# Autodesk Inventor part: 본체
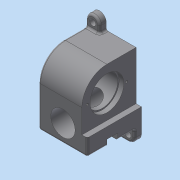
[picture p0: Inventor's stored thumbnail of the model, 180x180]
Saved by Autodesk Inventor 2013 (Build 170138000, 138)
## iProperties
Created: 2019-06
Part Number: 본체
Material: 알루미늄 6061
Document SubType Name: Modeling
Designer: mduedu
Density: 2.71 g/cm^3
Mass: 866.333 g
Surface Area: 555.001 cm^2
Volume: 319.68 cm^3
Author: mduedu
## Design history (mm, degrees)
sketch "스케치1"
  geometry: L1 (37, 0)-(37, -43); L2 (37, -43)-(-60, -43); L3 (-60, -43)-(-60, 37); L4 (-60, 37)-(0, 37); A1 r 37 centre (0, 0) between (37, 0) and (0, 37); 1 further point
  constraints: 8 end point, 2 point on circle, 2 tangent, 1 centre point, 1 coincident, 1 horizontal, 1 parallel, 1 perpendicular, 1 vertical
  dimensions: "d0" = 37 radius of A1; "d2" = 80 distance of L2.end L3.end; "d3" = 97 distance of L1.end L2.end
extrude "돌출1" new body sketch "스케치1" stored distance "d4" = 72; taper "d5" = 0 deg
sketch "스케치2"
  geometry: L1 (72, 25)-(64, 25); L2 (64, 25)-(64, 97); L3 (64, 97)-(72, 97); L4 (72, 97)-(72, 25); L5 (72, 97)-(0, 97) reference; L6 (72, 60)-(72, 0) reference; 1 further point
  constraints: 8 end point, 2 collinear, 2 parallel, 1 horizontal, 1 perpendicular
  dimensions: "d6" = 72 distance between parallel lines of L1 L3; "d8" = 8 distance of L1.start L1.end
extrude "돌출2" cut sketch "스케치2" stored distance "d9" = 72; taper "d10" = 0 deg
sketch "스케치3"
  geometry: L1 (-36, -60)-(-36, 37) reference; L2 (-36, 37)-(28, 37) reference; L3 (28, 37)-(28, -35) reference; L4 (28, -35)-(36, -35) reference; L5 (36, -35)-(36, -60) reference; L6 (36, -60)-(-36, -60) reference; L7 (-36, 0)-(-19, 0); L8 (-19, 0)-(-19, 17.5); L9 (-19, 17.5)-(-36, 17.5); L10 (-36, 17.5)-(-36, 0); L11 (-19, 0)-(21, 0); L12 (21, 0)-(21, 23); L13 (21, 23)-(-19, 23); L14 (-19, 23)-(-19, 0); L15 (21, 0)-(28, 0); L16 (28, 0)-(28, 25); L17 (28, 25)-(21, 25); L18 (21, 25)-(21, 0); 1 further point
  constraints: 24 end point, 6 parallel, 3 horizontal, 3 perpendicular, 2 point on line, 1 horizontal alignment
  dimensions: "d11" = 7 distance of L16.end L17.end; "d13" = 47 distance between parallel lines of L3 L8; "d14" = 50 diameter of L17 L15; "d15" = 46 diameter of L13 L11; "d16" = 35 diameter of L9 L7
revolve "회전1" sketch "스케치3" stored, may be unused: angle "d17" = 90 deg
sketch "스케치4"
  geometry: C1 r 28 at (0, 0); 1 further point
  constraints: 1 centre point, 1 coincident
  dimensions: "d18" = 56 diameter of C1
extrude "돌출3" cut sketch "스케치4" distance "d19" = 2; taper "d20" = 0 deg
fillet "모깎기1" dims "d21" = 3
sketch "스케치5"
  geometry: C1 r 18 at (36, 26); 1 further point
  constraints: 1 centre point, 1 vertical alignment
  dimensions: "d22" = 36 diameter of C1; "d23" = 34 distance of C1.centre point (36, 60)
extrude "돌출4" cut sketch "스케치5" stored distance "d24" = 2; taper "d25" = 0 deg
sketch "스케치6"
  geometry: L1 (-37, -60)-(43, -60) reference; L2 (-8, -60)-(8, -60); L3 (8, -60)-(8, -51); L4 (8, -51)-(-8, -51); L5 (-8, -51)-(-8, -60); 2 further points
  constraints: 8 end point, 2 parallel, 1 horizontal, 1 midpoint, 1 perpendicular, 1 point on line, 1 vertical alignment
  dimensions: "d26" = 16 distance between parallel lines of L3 L5; "d28" = 9 distance between parallel lines of L1 L4
extrude "돌출5" cut sketch "스케치6" stored distance "d29" = 2; taper "d30" = 0 deg
sketch "스케치7"
  geometry: L1 (-10, -60)-(10, -60); L2 (10, -60)-(10, -48.967); L3 (10, -48.967)-(-10, -48.967); L4 (-10, -48.967)-(-10, -60); L5 (36, -60)-(-36, -60) reference; 3 further points
  constraints: 8 end point, 2 parallel, 1 collinear, 1 horizontal, 1 midpoint, 1 perpendicular, 1 vertical alignment, 2 other
  dimensions: "d31" = 20 distance of L2.end L3.end
extrude "돌출6" cut sketch "스케치7" stored distance "d33" = 2; taper "d34" = 0 deg
sketch "스케치8"
  geometry: L1 (0, 25)-(8, 25) reference; L2 (8, 25)-(8, 60) reference; L3 (72, 60)-(8, 60) reference; L4 (72, 0)-(72, 60) reference; L5 (72, 0)-(0, 0) reference; L6 (0, 25)-(0, 0) reference; L7 (72, 0)-(0, 0); L8 (0, 0)-(0, -20); L9 (0, -20)-(72, -20); L10 (72, -20)-(72, 0); C1 r 18 at (36, 26) reference; 1 further point
  constraints: 8 end point, 2 parallel, 1 horizontal, 1 perpendicular, 1 point on line
  dimensions: "d35" = 20 distance of L7.end L8.end
extrude "돌출7" join sketch "스케치8" distance "d37" = 10; taper "d38" = 0 deg
sketch "스케치9"
  geometry: L1 (0, -37)-(0, 0) reference; L2 (0, 0)-(64, 0) reference; L3 (64, -37)-(64, 0) reference; L4 (44, 0)-(64, 0); L5 (64, 0)-(64, 20); L6 (64, 20)-(44, 20); L7 (44, 20)-(44, 0); 1 further point
  constraints: 9 end point, 2 perpendicular, 1 horizontal, 1 parallel
  dimensions: "d39" = 20 distance of L2.end L5.end; "d51" = 20 distance of L5.end L6.end
extrude "돌출8" join sketch "스케치9" distance "d41" = 10; taper "d42" = 0 deg
fillet "모깎기2" dims "d43" = 10
sketch "스케치10"
  geometry: L1 (-62, -20)-(-10, -20) reference; L2 (0, -10)-(0, 0) reference; L3 (-72, 0)-(0, 0) reference; L4 (-72, 0)-(-72, -10) reference; C1 r 4.5 at (-62, -10); C2 r 4.5 at (-10, -10); A1 r 10 centre (-62, -10) between (-72, -10) and (-62, -20) reference; A2 r 10 centre (-10, -10) between (-10, -20) and (0, -10) reference; 1 further point
  constraints: 2 centre point, 2 coincident, 1 equal radius
  dimensions: "d44" = 9 diameter of C1
extrude "돌출9" cut sketch "스케치10" stored distance "d45" = 10; taper "d46" = 0 deg
sketch "스케치11"
  geometry: L1 (-64, 10)-(-64, 0) reference; L2 (-44, 0)-(-64, 0) reference; L3 (-44, 0)-(-44, 10) reference; C1 r 4.5 at (-54, 10); A1 r 10 centre (-54, 10) between (-44, 10) and (-64, 10) reference; 1 further point
  constraints: 1 centre point, 1 coincident
  dimensions: "d47" = 9 diameter of C1
extrude "돌출10" cut sketch "스케치11" stored distance "d48" = 10; taper "d49" = 0 deg
fillet "모깎기4" dims "d52" = 3
fillet "모깎기5" dims "d53" = 3
fillet "모깎기6" dims "d54" = 3
fillet "모깎기7" dims "d55" = 3
sketch "스케치12" dims "d56" = 58
  geometry: 3 further points
  constraints: 2 horizontal alignment, 1 coincident, 2 other
hole "구멍1" sketch "스케치12" at (66, 35) diameter "d57" = 3.242; stored, may be unused: countersink angle "d61" = 90 deg, drill point angle "d63" = 118 deg; dims "d58" = 10, "d59" = 4, "d60" = 2, "d62" = 12
sketch "스케치13" dims "d67" = 44
  geometry: 3 further points
  constraints: 2 vertical alignment, 1 coincident, 2 other
hole "구멍2" sketch "스케치13" at (0, 22) diameter "d68" = 3.242; stored, may be unused: countersink angle "d72" = 90 deg, drill point angle "d74" = 118 deg; dims "d69" = 10, "d70" = 4, "d71" = 2, "d73" = 12
sketch "스케치14"
  geometry: 3 further points
  constraints: 2 horizontal alignment
  dimensions: "d78" = 25 distance of point (11, 8) point (36, 8); "d79" = 25 distance of point (61, 8) point (36, 8)
hole "구멍3" sketch "스케치14" at (11, 8), (61, 8) diameter "d80" = 3.242; stored, may be unused: countersink angle "d84" = 90 deg, drill point angle "d86" = 118 deg; dims "d81" = 8, "d82" = 4, "d83" = 2, "d85" = 10
node "솔리드1"
pattern_circular "원형 패턴1" dims angle "d65" = 360 deg
pattern_circular "원형 패턴2" dims angle "d76" = 360 deg
node "투영된 루프1"
node "투영된 루프2"
node "투영된 루프3"
node "절단 모서리 투영1"
